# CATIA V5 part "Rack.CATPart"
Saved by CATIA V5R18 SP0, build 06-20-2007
Part number: Part2
Bounding box of the stored display mesh (mm): x -50 to 50, y -15 to 20, z 15 to 70
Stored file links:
  D:\shriniwas\v5_r19\c16_CAT_v5r19\c16_Part\Rack Joint\Rack.CATPart
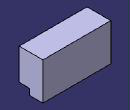
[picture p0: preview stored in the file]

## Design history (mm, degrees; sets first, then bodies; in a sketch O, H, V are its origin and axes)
Body1 (main body)
  Sketch1 on yz-plane, origin (0, 0, 0), H (0, 1, 0), V (0, 0, 1)
    line L1 (0, 15) -> (20, 15)
    point P1 (0, 15)
    reference intersected line E1 through (0, 0) direction (-1, 0) from xy-plane
    reference intersected line E3 through (0, 0) direction (0, 1) from zx-plane
    reference intersected line E4 through (0, 0) direction (-1, 0) from xy-plane
    reference intersected line E6 through (0, 0) direction (0, 1) from zx-plane
    point P3 (20, 70)
    line L2 (20, 70) -> (-15, 70)
    point P4 (-15, 70)
    reference intersected line E7 through (0, 0) direction (-1, 0) from xy-plane
    reference intersected line E9 through (0, 0) direction (0, 1) from zx-plane
    line L3 (20, 15) -> (20, 70)
    line L4 (-15, 70) -> (-15, 24)
    line L5 (-15, 24) -> (0, 24)
    point P6 (0, 24)
    line L6 (0, 15) -> (0, 24)
    distance E1 L1 = 15
    distance H L2 = 70
    distance P3 P4 = 35
    length L1 = 20
    length L6 = 9
    horizontal: L1 H, E1 H, E4 H, L2 H, E7 H, L5 H
    vertical: E3 V, E6 V, E9 V, L3 V, L4 V, L6 V
    coincidence: P1 V, P6 V
  Pad1: profile Sketch1, direction (1, 0, 0), length 50, mirrored extent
